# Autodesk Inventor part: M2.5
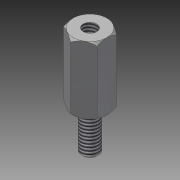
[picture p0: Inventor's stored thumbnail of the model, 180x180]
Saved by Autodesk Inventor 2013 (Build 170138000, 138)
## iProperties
Created: 2012-08
Part Number: M2.5
Material: Stahl
Document SubType Name: Modeling
Designer: rYan
Mass: 1.74537 g
Surface Area: 3.04272 cm^2
Volume: 0.22234 cm^3
Density: 7.85 g/cm^3
Author: rYan
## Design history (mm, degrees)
sketch "Skizze1"
  geometry: L1 (2.5, -1.443)-(0, -2.887); L2 (0, -2.887)-(-2.5, -1.443); L3 (-2.5, -1.443)-(-2.5, 1.443); L4 (-2.5, 1.443)-(0, 2.887); L5 (0, 2.887)-(2.5, 1.443); L6 (2.5, 1.443)-(2.5, -1.443); L7 (0, 4.041)-(0, -4.041) reference; 2 further points
  constraints: 12 end point, 1 coincident, 1 parallel, 13 other
  dimensions: "SW" = 5 distance between parallel lines of L3 L6
extrude "Extrusion1" new body sketch "Skizze1" taper "d2" = 0 deg; stored distance "L" = 10
sketch "Skizze2"
  geometry: 2 further points
  constraints: 1 coincident
hole "Bohrung1" sketch "Skizze2" at (0, 0) diameter "d3" = 2.013; stored, may be unused: countersink angle "d7" = 90 deg, drill point angle "d9" = 118 deg; dims "d4" = 6, "d5" = 4, "d6" = 2, "l_" = 7
sketch "Skizze3"
  geometry: C1 r 1.25 at (0, 0); 1 further point
  constraints: 1 centre point, 1 coincident
  dimensions: "GA_" = 2.5 diameter of C1
extrude "Extrusion2" join sketch "Skizze3" taper "d13" = 0 deg; distance "A_" = 6
feature "Gewinde1" dims "d14" = 5, "d15" = 0
chamfer "Fase1" distance "d17" = 0.25; stored, may be unused: second distance "d18" = 2, angle "d19" = 45 deg
sketch "Skizze4"
  geometry: L1 (2.5, -1.443)-(2.5, 1.443) reference; C1 r 2.5 at (0, 0); 1 further point
  constraints: 1 centre point, 1 coincident, 1 tangent
sketch "Skizze5"
  geometry: L1 (-1.006, 5)-(1.006, 5) reference; L2 (-2.887, 5)-(-1.443, 5) reference; L3 (-1.443, 5)-(1.443, 5) reference; L4 (1.443, 5)-(2.887, 5) reference; L5 (2.887, 5)-(1.443, 5) reference; L6 (1.443, 5)-(-1.443, 5) reference; L7 (-1.443, 5)-(-2.887, 5) reference; L8 (2.887, 5)-(2.5, 5); L9 (2.5, 5)-(2.887, 4.613); L10 (2.887, 4.613)-(2.887, 5); L11 (0, 7)-(0, -7) reference; L12 (1.25, -5)-(-1.25, -5) reference; L13 (-1.443, -5)-(-2.887, -5) reference; L14 (-2.887, -5)-(-1.443, -5) reference; L15 (-1.443, -5)-(1.443, -5) reference; L16 (1.443, -5)-(2.887, -5) reference; L17 (2.887, -5)-(1.443, -5) reference; L18 (1.443, -5)-(-1.443, -5) reference; L19 (0, 5)-(0, -5); 2 further points; 1 other entity
  constraints: 8 end point, 1 collinear, 1 midpoint, 1 perpendicular, 1 point on line, 2 other
  dimensions: "d20" = 45 deg angle of L8 L9
revolve "Umdrehung1" sketch "Skizze5" stored, may be unused: angle "d21" = 90 deg
mirror "Spiegeln1"
node "Volumenkörper1"
node "Projizierte Kontur1"
node "Projizierte Kontur2"
